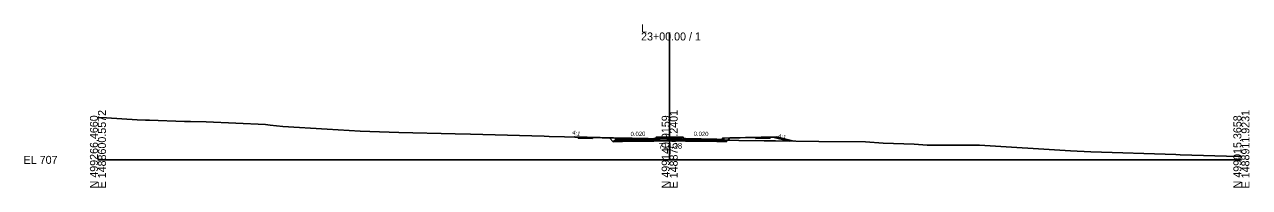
# Model space of a CAD drawing. Extents: x -26 to 4203, y -10 to 9538.
# Drawn here: x 974.3 to 1402.8, y 1990.3 to 2047.4 of the extents above; entities that cross this region are included whole.
import ezdxf

# ---------------------------------------------------------------- set-up
doc = ezdxf.new("R2010")
doc.units = 0
for name, color, linetype in [('Default', 7, 'Continuous'), ('Exist Horizontal Alignment', 7, 'Continuous'), ('Prop Grid Mask', 7, 'Continuous'), ('Prop Horizontal Alignment', 7, 'Continuous'), ('Prop Horizontal Alignment Curve and Spiral Data', 7, 'Continuous'), ('Prop Horizontal Alignment Station Label', 7, 'Continuous'), ('Prop Horizontal Alignment Tick Label', 7, 'Continuous'), ('Prop Horizontal Alignment Tick Large', 7, 'Continuous'), ('Prop Horizontal Alignment Tick Small', 7, 'Continuous'), ('Scratch_Level_4', 7, 'Continuous'), ('Scratch_Level_5', 7, 'Continuous'), ('Sheet Border Standard 30in CELL', 7, 'Continuous'), ('Sheet Cutting Line CELL', 7, 'Continuous'), ('Sheet Data Field CELL', 7, 'Continuous'), ('Sheet Plot Border Inside CELL', 7, 'Continuous'), ('Sheet Plot Border Outside CELL', 7, 'Continuous')]:
    doc.layers.add(name, color=color, linetype=linetype)

msp = doc.modelspace()

# ---------------------------------------------------------------- linework, layer by layer
at = {"layer": 'Exist Horizontal Alignment'}
msp.add_lwpolyline([(1000, 2014.88), (1002.95, 2014.76), (1013.74, 2014.08), (1016.61, 2013.94), (1017.98, 2013.87), (1030.32, 2013.46), (1032.32, 2013.46), (1037.91, 2013.31), (1058.62, 2012.4), (1060.2, 2012.19), (1064.71, 2011.63), (1080.22, 2010.77), (1091.76, 2010.11), (1105.29, 2009.6), (1125.02, 2009.11), (1130.27, 2008.99), (1134.64, 2008.87), (1156.09, 2008.28), (1157.88, 2008.23), (1184.86, 2007.6), (1186.93, 2007.56), (1199.02, 2007.29), (1200, 2007.28), (1201.79, 2007.26), (1202.68, 2007.27), (1203.37, 2007.25), (1206.74, 2007.22), (1209.73, 2007.2), (1213.15, 2007.17), (1214.67, 2007.11), (1224.19, 2006.79), (1233.11, 2006.69), (1236.98, 2006.61), (1244.14, 2006.51), (1252.17, 2006.38), (1268.51, 2006.27), (1274.7, 2005.85), (1285.55, 2005.5), (1290.12, 2005.19), (1301.51, 2005.2), (1308.37, 2005.19), (1340.22, 2003.11), (1347.3, 2002.84), (1377.11, 2001.84), (1378.53, 2001.79), (1398.85, 2001.2), (1400, 2001.16)], dxfattribs=at)
at = {"layer": 'Prop Horizontal Alignment Curve and Spiral Data'}
for points in [[(1183.5, 2006.42), (1180.24, 2006.36), (1178.93, 2007.68)], [(1194.5, 2006.6), (1183.5, 2006.38)], [(1183.5, 2006.38), (1183.5, 2006.42)], [(1196.76, 2006.69), (1194.5, 2006.64)], [(1194.5, 2006.64), (1194.5, 2006.6)], [(1194.5, 2006.6), (1194.5, 2006.6)], [(1196.76, 2006.69), (1203.24, 2006.69)], [(1203.24, 2006.69), (1205.5, 2006.64)], [(1205.5, 2006.64), (1205.5, 2006.6)], [(1205.5, 2006.6), (1205.5, 2006.6)], [(1205.5, 2006.6), (1216.5, 2006.38)], [(1216.5, 2006.42), (1219.76, 2006.36), (1221.08, 2007.68)], [(1216.5, 2006.38), (1216.5, 2006.42)]]:
    msp.add_lwpolyline(points, dxfattribs=at)
at = {"layer": 'Prop Horizontal Alignment Station Label'}
msp.add_line((1236.11, 2007.98), (1241.85, 2006.54), dxfattribs=at)
for points in [[(1181, 2007.64), (1167, 2007.92), (1166.57, 2008.02)], [(1219, 2007.64), (1236.11, 2007.98)]]:
    msp.add_lwpolyline(points, dxfattribs=at)
at = {"layer": 'Prop Horizontal Alignment Tick Label'}
for points in [[(1194.5, 2007.23), (1183.5, 2007.01)], [(1183.5, 2007.01), (1183.5, 2006.76)], [(1183.5, 2006.76), (1194.5, 2006.98)], [(1194.5, 2006.98), (1194.5, 2007.23)], [(1205.5, 2006.98), (1205.5, 2007.23)], [(1205.5, 2007.23), (1216.5, 2007.01)], [(1216.5, 2006.76), (1205.5, 2006.98)], [(1216.5, 2007.01), (1216.5, 2006.76)]]:
    msp.add_lwpolyline(points, dxfattribs=at)
at = {"layer": 'Prop Horizontal Alignment Tick Large'}
for points in [[(1194.5, 2006.98), (1183.5, 2006.76)], [(1183.5, 2006.76), (1183.5, 2006.38)], [(1183.5, 2006.38), (1194.5, 2006.6)], [(1194.5, 2006.6), (1194.5, 2006.98)], [(1205.5, 2006.98), (1216.5, 2006.76)], [(1205.5, 2006.6), (1205.5, 2006.98)], [(1216.5, 2006.38), (1205.5, 2006.6)], [(1216.5, 2006.76), (1216.5, 2006.38)]]:
    msp.add_lwpolyline(points, dxfattribs=at)
at = {"layer": 'Prop Horizontal Alignment Tick Small'}
for p, q in [((1200, 2000), (1200, 2025.39)), ((1168, 2007.56), (1168, 2007.9)), ((1173, 2007.46), (1173, 2007.8)), ((1196.01, 2007.49), (1203.99, 2007.49)), ((1230.11, 2007.52), (1230.11, 2007.86)), ((1230.11, 2007.52), (1235.11, 2007.62)), ((1235.11, 2007.62), (1235.11, 2007.96))]:
    msp.add_line(p, q, dxfattribs=at)
for points in [[(1173, 2007.46), (1168, 2007.56)], [(1183.5, 2007.26), (1181.5, 2007.14), (1181.5, 2007.64), (1181, 2007.64)], [(1181, 2007.64), (1181, 2006.62), (1183.5, 2006.67)], [(1183.5, 2006.67), (1183.5, 2007.26)], [(1194.5, 2007.48), (1195.25, 2007.49), (1195.25, 2007.91), (1196.01, 2007.91)], [(1194.5, 2006.89), (1194.5, 2007.48)], [(1196.01, 2006.92), (1194.5, 2006.89)], [(1196.01, 2007.91), (1196.01, 2006.92)], [(1196.01, 2007.91), (1203.99, 2007.91)], [(1203.99, 2007.91), (1203.99, 2006.92)], [(1203.99, 2006.92), (1205.5, 2006.89)], [(1205.5, 2006.89), (1205.5, 2007.48)], [(1216.5, 2007.26), (1218.5, 2007.14), (1218.5, 2007.64), (1219, 2007.64)], [(1219, 2007.64), (1219, 2006.62), (1216.5, 2006.67)], [(1216.5, 2006.67), (1216.5, 2007.26)]]:
    msp.add_lwpolyline(points, dxfattribs=at)
at = {"layer": 'Scratch_Level_4'}
for p, q in [((1200, 2000), (1200, 2044.63)), ((1000, 2000), (1200, 2000)), ((1200, 2000), (1400, 2000))]:
    msp.add_line(p, q, dxfattribs=at)
at = {"layer": 'Sheet Border Standard 30in CELL'}
for points in [[(1194.5, 2007.48), (1183.5, 2007.26)], [(1205.5, 2007.48), (1216.5, 2007.26)]]:
    msp.add_lwpolyline(points, dxfattribs=at)
at = {"layer": 'Sheet Cutting Line CELL'}
for points in [[(1181.5, 2007.14), (1181.5, 2007.64), (1181, 2007.64), (1178.93, 2007.68), (1167, 2007.92), (1166.57, 2008.02), (1184.86, 2007.6), (1186.93, 2007.56), (1192.43, 2007.43), (1183.5, 2007.26)], [(1205.5, 2006.64), (1205.5, 2006.6), (1216.5, 2006.38), (1216.5, 2006.42), (1219.76, 2006.36), (1220.32, 2006.92), (1214.67, 2007.11), (1213.15, 2007.17), (1209.73, 2007.2), (1206.74, 2007.22), (1203.37, 2007.25), (1202.68, 2007.27), (1201.79, 2007.26), (1200, 2007.28), (1199.02, 2007.29), (1192.43, 2007.43), (1183.5, 2007.26), (1181.5, 2007.14), (1181.5, 2007.64), (1181, 2007.64), (1178.93, 2007.68), (1180.24, 2006.36), (1183.5, 2006.42), (1183.5, 2006.38), (1194.5, 2006.6), (1194.5, 2006.64), (1196.76, 2006.69), (1203.24, 2006.69)], [(1224.19, 2006.79), (1233.11, 2006.69), (1236.98, 2006.61), (1243.45, 2006.52), (1237.5, 2008.01), (1221.08, 2007.68), (1220.32, 2006.92)]]:
    msp.add_lwpolyline(points, close=True, dxfattribs=at)
at = {"layer": 'Sheet Data Field CELL'}
for points in [[(1183.5, 2006.67), (1180.5, 2006.61), (1180.24, 2006.36)], [(1180.24, 2006.36), (1183.5, 2006.42)], [(1183.5, 2006.42), (1183.5, 2006.67)], [(1194.5, 2006.89), (1196.51, 2006.93), (1196.76, 2006.69)], [(1194.5, 2006.64), (1194.5, 2006.89)], [(1196.76, 2006.69), (1194.5, 2006.64)], [(1205.5, 2006.89), (1203.49, 2006.93), (1203.24, 2006.69)], [(1203.24, 2006.69), (1205.5, 2006.64)], [(1205.5, 2006.64), (1205.5, 2006.89)], [(1216.5, 2006.67), (1219.5, 2006.61), (1219.76, 2006.36)], [(1216.5, 2006.42), (1216.5, 2006.67)], [(1219.76, 2006.36), (1216.5, 2006.42)]]:
    msp.add_lwpolyline(points, dxfattribs=at)
at = {"layer": 'Sheet Plot Border Inside CELL'}
for points in [[(1194.5, 2007.48), (1183.5, 2007.26)], [(1183.5, 2007.26), (1183.5, 2007.01)], [(1183.5, 2007.01), (1194.5, 2007.23)], [(1194.5, 2007.23), (1194.5, 2007.48)], [(1194.5, 2007.23), (1194.5, 2007.23), (1194.5, 2007.23)], [(1205.5, 2007.48), (1216.5, 2007.26)], [(1205.5, 2007.23), (1205.5, 2007.48)], [(1216.5, 2007.01), (1205.5, 2007.23)], [(1205.5, 2007.23), (1205.5, 2007.23), (1205.5, 2007.23)], [(1216.5, 2007.26), (1216.5, 2007.01)]]:
    msp.add_lwpolyline(points, dxfattribs=at)
at = {"layer": 'Sheet Plot Border Outside CELL'}
for points in [[(1181.5, 2007.14), (1181.5, 2007.64), (1181, 2007.64)], [(1183.5, 2007.26), (1181.5, 2007.14)], [(1205.5, 2007.48), (1204.75, 2007.49), (1204.75, 2007.91), (1203.99, 2007.91)], [(1216.5, 2007.26), (1218.5, 2007.14)], [(1218.5, 2007.14), (1218.5, 2007.64), (1219, 2007.64)]]:
    msp.add_lwpolyline(points, dxfattribs=at)

# ---------------------------------------------------------------- texts
at = {"layer": 'Default'}
msp.add_text('-', height=0.0001, dxfattribs=at).set_placement((1000, 2000))
msp.add_text('-', height=0.0001, dxfattribs=at).set_placement((1000, 2000))
msp.add_text('-', height=0.0001, dxfattribs=at).set_placement((1000, 2000))
at = {"layer": 'Prop Grid Mask'}
for p in [(1165.8, 2008.99), (1237.79, 2007.75)]:
    msp.add_text('4:1', height=1.5, rotation=345.9638, dxfattribs=at).set_placement(p)
at = {"layer": 'Prop Horizontal Alignment'}
msp.add_text('714.28', height=2, dxfattribs=at).set_placement((1196.18, 2003.94))
at = {"layer": 'Scratch_Level_4'}
for s, p in [('23+00.00 / 1', (1190, 2041.83)), ('L', (1190, 2044.63)), ('EL 707', (974, 1998.6))]:
    msp.add_text(s, height=2.8, dxfattribs=at).set_placement(p)
for s, p in [('N 499266.4660', (1000, 1990)), ('E 1488600.5572', (1002.8, 1990)), ('N 499140.9159', (1200, 1990)), ('E 1488756.2401', (1202.8, 1990)), ('N 499015.3658', (1400, 1990)), ('E 1488911.9231', (1402.8, 1990))]:
    msp.add_text(s, height=2.8, rotation=90, dxfattribs=at).set_placement(p)
at = {"layer": 'Scratch_Level_5'}
for rotation, p in [(1.1458, (1186.34, 2008.31)), (358.8542, (1208.38, 2008.42))]:
    msp.add_text('0.020', height=1.5, rotation=rotation, dxfattribs=at).set_placement(p)

doc.saveas('drawing.dxf')
